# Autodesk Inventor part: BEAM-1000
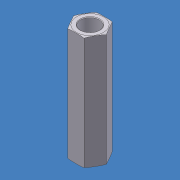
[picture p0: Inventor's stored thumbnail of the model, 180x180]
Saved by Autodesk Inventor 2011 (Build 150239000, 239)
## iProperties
Created: 2007-08
Part Number: BEAM-1000
Material: Aluminum-6061
Document SubType Name: Modeling
Density: 2.71 g/cm^3
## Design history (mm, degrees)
feature "Base1"
body "Solid1"
